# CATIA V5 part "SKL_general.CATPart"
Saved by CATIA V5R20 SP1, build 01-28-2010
Part number: SKL_general
Property "bielle1": 100 mm
Property "bielle2": 360 mm
Property "bielle3": 520 mm
Property "bielle4": 360 mm
Property "bielle5": 1140 mm
Property "GA": 1100 mm
Property "GD": 840 mm
Property "BC": 200 mm
Property "bielle_1": 100 mm
Property "bielle_2": 360 mm
Property "bielle_3": 520 mm
Property "bielle_4": 360 mm
Property "bielle_5": 1140 mm
Property "ga": 1100 mm
Property "gd": 840 mm
Property "bc": 200 mm
Publications: "G", "D", "B", "C", "E", "A", "F"
Bounding box of the stored display mesh (mm): x -1140 to 1188.11, y -1139.837 to 1178.682, z 0 to 0
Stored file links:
  C:\Users\Manon\Desktop\IAO\SKL_rlanglais\SKL_general.CATPart
  C:\Users\Manon\Desktop\IAO\SKL_rlanglais\SKL_rlanglais.CATProduct
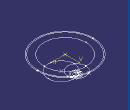
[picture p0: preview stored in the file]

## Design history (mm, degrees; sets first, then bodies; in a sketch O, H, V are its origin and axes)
Set1
  Point1 "G": type OnPlane, Support xy-plane, H 0, V 0, Direction (1, 0, 0)
  Point2 "D": (0, 0, 0), relative to Sketch1.P2
  Point3 "B": (0, 0, 0), relative to Sketch1.P9
  Point4 "C": (0, 0, 0), relative to Sketch1.P3
  Point5 "E": (0, 0, 0), relative to Sketch1.P6
  Point6 "A": (0, 0, 0), relative to Sketch1.P8
  Point7 "F": (0, 0, 0), relative to Sketch1.P7
Body1 (main body)
  Sketch1 on xy-plane, origin (0, 0, 0), H (1, 0, 0), V (0, 1, 0)
    circle A1 centre (0, 0) radius 840
    circle A2 centre (0, 0) radius 1100
    circle A3 centre (668.1104, 509.1449) radius 520
    point P1 (668.1104, 509.1449)
    point P2 (668.1104, 509.1449)
    point P3 (638.046, 1028.275)
    circle A4 centre (475.437, 911.8348) radius 200
    point P4 (475.437, 911.8348)
    circle A5 centre (475.437, 911.8348) radius 160
    axis line L1 (638.046, 1028.275) -> (-213.0282, 418.8417)
    point P6 (345.3499, 818.6826)
    circle A6 centre (345.3499, 818.6826) radius 360
    circle A7 centre (0, 0) radius 1140
    point P7 (161.9147, 1128.443)
    circle A8 centre (475.437, 911.8348) radius 100
    point P8 (443.5439, 1006.6125)
    point P9 (475.437, 911.8348)
    radius A1 = 840
    radius A2 = 1100
    radius A3 = 520
    radius A4 = 200
    radius A5 = 160
    radius A6 = 360
    radius A7 = 1140
    radius A8 = 100
    coincidence: P1 A1, P2 P1, P3 A3, A4 P3, L1 P4, P6 A5, P6 L1, P7 A7, P7 A6, P8 A8, P8 A2, P9 L1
